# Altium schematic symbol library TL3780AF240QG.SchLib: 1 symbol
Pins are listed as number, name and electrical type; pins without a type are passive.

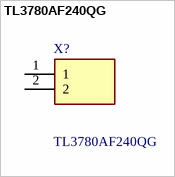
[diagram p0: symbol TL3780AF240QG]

## TL3780AF240QG
designator X?
Tactile Switches 20mA 15VDC 240gf SPST 2x3mm Gull SMT; Manufacturer_Name: E-Switch; Geometry.Height: 0.6mm
footprint TL3780AF240QG
pins: 1, 2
